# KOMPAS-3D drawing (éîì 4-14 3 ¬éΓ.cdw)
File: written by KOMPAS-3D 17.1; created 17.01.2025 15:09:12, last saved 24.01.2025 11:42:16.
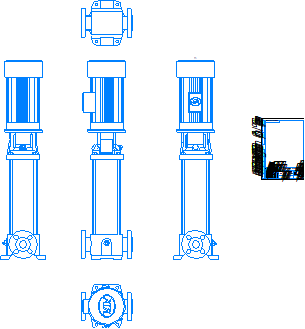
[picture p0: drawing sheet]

Sheet 1: A4, portrait

Title block, sheet 1: name: ВМН 4-14 3 кВт; designation: ВМН 4-14 3 кВт; sheets: 1; sheet format: A4; stored path: \\adlc.lan\data\АДЛ_ПКД\3D-модели\ADL production\Насосы ГРАНПАМП\Насосы ВМН\ВМН4\KOMPAS 2D\ВМН 4-14 3 кВт.cdw

Views: Проекционный вид 2, Проекционный вид 3, Проекционный вид 4, Проекционный вид 5
Referenced files in \\adlc.lan\data\АДЛ_ПКД\3D-модели\ADL production\Насосы ГРАНПАМП\Насосы ВМН\ВМН4\KOMPAS 3D\: ВМН 4-14 3,0 кВт.m3d
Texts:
  Andrey
  АДЛ
Dimensions and other numbers on the sheet: 1:1; 1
